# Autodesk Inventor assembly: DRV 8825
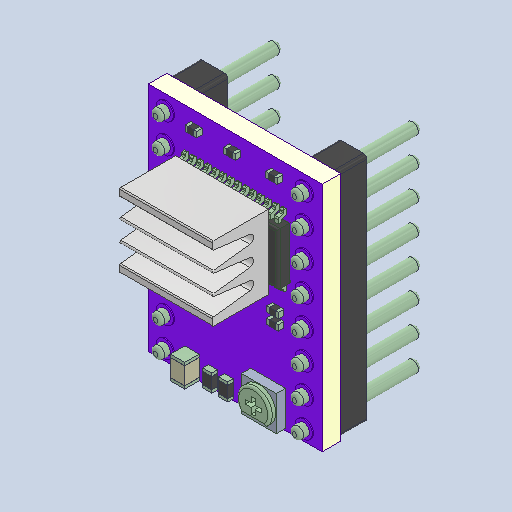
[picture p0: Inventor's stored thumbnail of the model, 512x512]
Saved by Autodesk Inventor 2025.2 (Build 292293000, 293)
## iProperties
Created: 2025-04
Part Number: DRV 8825
Description: PART--DESC
Document SubType Name: Assembly
Designer: BennF
Author: BennF
Revision Number: NONE
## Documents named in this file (9)
- C:\Users\BennF\Nextcloud\Benutzer\CNC JarBeRi\existing parts\Electronics\RepRap A4988 Shied (USE WITHOUT ARDUINO)\reprap-a4988-1.snapshot.1\RepRap\RepRap\DRV 8825_1.iam
- C:\Users\BennF\Nextcloud\Benutzer\CNC JarBeRi\existing parts\Electronics\RepRap A4988 Shied (USE WITHOUT ARDUINO)\reprap-a4988-1.snapshot.1\RepRap\RepRap\DRV 8825 Geometry.ipt
- C:\Users\BennF\Nextcloud\Benutzer\CNC JarBeRi\existing parts\Electronics\RepRap A4988 Shied (USE WITHOUT ARDUINO)\reprap-a4988-1.snapshot.1\RepRap\RepRap\PCB.ipt
- C:\Users\BennF\Nextcloud\Benutzer\CNC JarBeRi\existing parts\Electronics\RepRap A4988 Shied (USE WITHOUT ARDUINO)\reprap-a4988-1.snapshot.1\RepRap\RepRap\SMD Pot.ipt
- C:\Users\BennF\Nextcloud\Benutzer\CNC JarBeRi\existing parts\Electronics\RepRap A4988 Shied (USE WITHOUT ARDUINO)\reprap-a4988-1.snapshot.1\RepRap\RepRap\0603 Resistor.ipt
- C:\Users\BennF\Nextcloud\Benutzer\CNC JarBeRi\existing parts\Electronics\RepRap A4988 Shied (USE WITHOUT ARDUINO)\reprap-a4988-1.snapshot.1\RepRap\RepRap\0805 Capacitor.ipt
- C:\Users\BennF\Nextcloud\Benutzer\CNC JarBeRi\existing parts\Electronics\RepRap A4988 Shied (USE WITHOUT ARDUINO)\reprap-a4988-1.snapshot.1\RepRap\RepRap\0402 Resistor.ipt
- C:\Users\BennF\Nextcloud\Benutzer\CNC JarBeRi\existing parts\Electronics\RepRap A4988 Shied (USE WITHOUT ARDUINO)\reprap-a4988-1.snapshot.1\RepRap\RepRap\DRV8825 IC.ipt
- C:\Users\BennF\Nextcloud\Benutzer\CNC JarBeRi\existing parts\Electronics\RepRap A4988 Shied (USE WITHOUT ARDUINO)\reprap-a4988-1.snapshot.1\RepRap\RepRap\8 pin Header.ipt
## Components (16 placed, 8 different names)
1. DRV 8825 Geometry
2. PCB
3. SMD Pot
4. 0603 Resistor
5. 0603 Resistor:1
6. 0805 Capacitor
7. 0402 Resistor
8. 0402 Resistor:1
9. 0402 Resistor:2
10. 0402 Resistor:3
11. 0402 Resistor:4
12. 0402 Resistor:5
13. 0402 Resistor:6
14. DRV8825 IC
15. 8 pin Header
16. 8 pin Header:1
